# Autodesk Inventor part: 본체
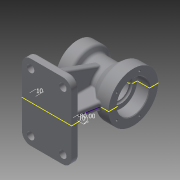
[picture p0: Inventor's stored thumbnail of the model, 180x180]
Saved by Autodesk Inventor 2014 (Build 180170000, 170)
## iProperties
Created: 2015-08
Part Number: 본체
Material: 일반
Document SubType Name: Modeling
Designer: Owner
Density: 1 g/cm^3
Appearance: 기본값
Author: Owner
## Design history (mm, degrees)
sketch "스케치1"
  geometry: L1 (-45, 0)-(45, 0); L2 (-45, 20)-(-45, 35); L3 (-45, 35)-(-25, 35); L4 (-25, 35)-(-19.804, 26); L5 (-19.804, 26)-(8.315, 26); L6 (8.315, 26)-(25, 40); L7 (25, 40)-(45, 40); L8 (45, 40)-(45, 26); L9 (45, 26)-(25, 26); L10 (22, 16)-(-28, 16); L11 (-28, 20)-(-45, 20); L12 (-28, 20)-(-28, 16); L13 (25, 26)-(25, 19); L14 (25, 19)-(22, 19); L15 (22, 19)-(22, 16); 2 further points
  constraints: 30 end point, 8 parallel, 4 perpendicular, 2 vertical alignment, 1 coincident, 1 horizontal, 1 midpoint
  dimensions: "d0" = 90 distance of L1.start L1.end; "d1" = 20 distance of L2.end L3.end; "d2" = 20 distance of L6.end L7.end; "d3" = 70 diameter of L3 L1; "d4" = 80 diameter of L7 L1; "d5" = 52 diameter of L5 L1; "d6" = 60 deg angle of L4 L5; "d7" = 40 deg angle of L5 L6; "d8" = 40 diameter of L11 L1; "d9" = 17 distance from line of L1.start L12; "d10" = 32 diameter of L10 L1; "d11" = 38 diameter of L14 L1; "d12" = 3 distance of L13.end L14.end; "d13" = 20 distance of L8.end L9.end; "d14" = 52 diameter of L9 L1
revolve "회전1" sketch "스케치1" stored, may be unused: angle "d15" = 90 deg
node "작업 평면1"
sketch "스케치2"
  geometry: L1 (25, 35)-(25, -35) reference; L2 (45, 35)-(45, -35) reference; L3 (45, 35)-(45, -35) reference; L4 (45, 35)-(25, 35) reference; L5 (45, -35)-(25, -35) reference; L6 (-35, 61)-(45, 61); L7 (45, 61)-(45, -61); L8 (45, -61)-(-35, -61); L9 (-35, -61)-(-35, 61); 2 further points
  constraints: 8 end point, 2 parallel, 1 collinear, 1 horizontal, 1 horizontal alignment, 1 midpoint, 1 perpendicular
  dimensions: "d17" = 80 distance of L7.end L8.end; "d18" = 122 distance of L6.end L7.end
extrude "돌출1" join sketch "스케치2" distance "d20" = 12; taper "d21" = 0 deg
node "작업 평면2"
sketch "스케치3"
  geometry: L1 (0, 0)-(0, 12) reference; L2 (0, 12)-(122, 12) reference; L3 (122, 12)-(122, 0) reference; L4 (122, 0)-(0, 0) reference; L5 (61, -26)-(61, 156) reference; L6 (10, 12)-(35.909, 83.185); L7 (86.091, 83.185)-(112, 12); C1 r 16 at (61, 90) reference; A1 r 26 centre (61, 90) between (35.909, 83.185) and (86.091, 83.185) reference; 1 further point
  constraints: 4 end point, 2 point on circle, 2 point on line
  dimensions: "d22" = 70 deg angle of L2 L6; "d23" = 10 distance of L6.start L1.end; "d24" = 70 deg angle of L7 L2; "d25" = 10 distance of L7.end L2.end
extrude "돌출2" join sketch "스케치3" stored distance "d26" = 12; taper "d27" = 0 deg
sketch "스케치4"
  geometry: L1 (35, 61)-(-45, 61) reference; L2 (-45, 61)-(-45, -61) reference; C1 r 6 at (-31, 47); 1 further point
  constraints: 1 centre point
  dimensions: "d28" = 12 diameter of C1; "d29" = 14 distance from line of C1.centre L1; "d30" = 14 distance from line of C1.centre L2
extrude "돌출3" cut sketch "스케치4" stored distance "d31" = 12; taper "d32" = 0 deg
fillet "모깎기1" dims "d39" = 14
node "작업 평면3"
sketch "스케치5"
  geometry: L1 (-14, 125)-(6, 125) reference; L2 (6, 125)-(11.196, 116) reference; L3 (11.196, 116)-(39.315, 116) reference; L4 (39.315, 116)-(56, 130) reference; L5 (56, 130)-(76, 130) reference; L6 (76, 130)-(76, 116) reference; L7 (76, 116)-(56, 116) reference; L8 (56, 116)-(56, 109) reference; L9 (56, 109)-(53, 109) reference; L10 (53, 109)-(53, 106) reference; L11 (53, 106)-(3, 106) reference; L12 (3, 106)-(3, 110) reference; L13 (3, 110)-(-14, 110) reference; L14 (-14, 110)-(-14, 125) reference; L15 (6, 55)-(-14, 55) reference; L16 (-14, 55)-(-14, 70) reference; L17 (-14, 70)-(3, 70) reference; L18 (3, 70)-(3, 74) reference; L19 (3, 74)-(53, 74) reference; L20 (53, 74)-(53, 71) reference; L21 (53, 71)-(56, 71) reference; L22 (56, 71)-(56, 64) reference; L23 (56, 64)-(76, 64) reference; L24 (76, 64)-(76, 50) reference; L25 (76, 50)-(56, 50) reference; L26 (56, 50)-(39.315, 64) reference; L27 (39.315, 64)-(32, 64) reference; L28 (32, 64)-(32, 12) reference; L29 (32, 12)-(66, 12) reference; L30 (66, 12)-(66, 0) reference; L31 (66, 0)-(-14, 0) reference; L32 (-14, 0)-(-14, 12) reference; L33 (-14, 12)-(20, 12) reference; L34 (20, 12)-(20, 64) reference; L35 (20, 64)-(11.196, 64) reference; L36 (11.196, 64)-(6, 55) reference; L37 (-14, 125)-(6, 125) reference; L38 (6, 125)-(11.196, 116) reference; L39 (11.196, 116)-(39.315, 116) reference; L40 (39.315, 116)-(56, 130) reference; L41 (56, 130)-(76, 130) reference; L42 (76, 130)-(76, 116) reference; L43 (76, 116)-(56, 116) reference; L44 (56, 116)-(56, 109) reference; L45 (56, 109)-(53, 109) reference; L46 (53, 109)-(53, 106) reference; L47 (53, 106)-(3, 106) reference; L48 (3, 106)-(3, 110) reference; L49 (3, 110)-(-14, 110) reference; L50 (-14, 110)-(-14, 125) reference; L51 (6, 55)-(-14, 55) reference; L52 (-14, 55)-(-14, 70) reference; L53 (-14, 70)-(3, 70) reference; L54 (3, 70)-(3, 74) reference; L55 (3, 74)-(53, 74) reference; L56 (53, 74)-(53, 71) reference; L57 (53, 71)-(56, 71) reference; L58 (56, 71)-(56, 64) reference; L59 (56, 64)-(76, 64) reference; L60 (76, 64)-(76, 50) reference; L61 (76, 50)-(56, 50) reference; L62 (56, 50)-(39.315, 64) reference; L63 (39.315, 64)-(32, 64) reference; L64 (32, 64)-(32, 12) reference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; 1 further point
  constraints: 4 end point, 3 point on line, 1 midpoint, 1 perpendicular
  dimensions: "d40" = 10 distance from line of L32 L73.start; "d41" = 10 distance from line of L74.start L30; "d42" = 80 deg angle of L74 L29
  node "절단 모서리 투영2"
  node "절단 모서리 투영3"
feature "리브1" dims "d43" = 1, "d44" = 12, "d45" = 0, "d46" = 0, "d47" = 1, "d48" = 1
feature "리브2" dims "d49" = 1, "d50" = 12, "d51" = 0, "d52" = 0, "d53" = 1, "d54" = 1
sketch "스케치6"
  geometry: C1 r 40 at (0, 0) reference; 1 further point
  constraints: 1 vertical alignment
  dimensions: "d55" = 33 distance of point (0, 33) C1.centre
hole "구멍1" sketch "스케치6" at (0, 33) diameter "d56" = 3.242; stored, may be unused: countersink angle "d60" = 90 deg, drill point angle "d62" = 118 deg; dims "d57" = 10, "d58" = 4, "d59" = 2, "d61" = 13
sketch "스케치7"
  geometry: C1 r 35 at (0, 0) reference; 1 further point
  constraints: 1 vertical alignment
  dimensions: "d66" = 27 distance of point (0, 27) C1.centre
hole "구멍2" sketch "스케치7" at (0, 27) diameter "d67" = 3.242; stored, may be unused: countersink angle "d71" = 90 deg, drill point angle "d73" = 118 deg; dims "d68" = 10, "d69" = 4, "d70" = 2, "d72" = 13
sketch "스케치8"
  geometry: L1 (112, 12)-(67, 12) reference; L2 (43, 30)-(43, 36); L3 (31, 30)-(31, 36); L4 (14, 12)-(108, 12) reference; A1 r 26 centre (61, 90) between (67, 64.702) and (86.091, 83.185) reference; A2 r 6 centre (37, 30) between (31, 30) and (43, 30); A3 r 6 centre (37, 36) between (43, 36) and (31, 36)
  constraints: 4 end point, 4 point on circle, 2 centre point, 2 tangent, 1 parallel, 1 perpendicular, 1 vertical alignment
  dimensions: "d77" = 12 diameter of A2; "d78" = 12 diameter of A3; "d79" = 24 horizontal distance of A3.centre A1.centre; "d80" = 18 distance from line of A2.centre L4; "d81" = 18 dimension on A2 A3
extrude "돌출4" cut sketch "스케치8" stored distance "d82" = 12; taper "d83" = 0 deg
node "작업 평면4"
fillet "모깎기2" dims "d84" = 0.3
chamfer "모따기1" distance "d85" = 1; stored, may be unused: second distance "d86" = 2, angle "d87" = 45 deg
fillet "모깎기3" dims "d88" = 3
fillet "모깎기4" dims "d89" = 3
fillet "모깎기5" dims "d90" = 5
fillet "모깎기6" dims "d91" = 3
sketch "스케치9"
  geometry: L1 (-3, 37.119)-(-3, 0) reference; L2 (53, -3)-(1, -3) reference; 2 further points
  constraints: 1 other
  dimensions: "d92" = 16 distance from line of point (13, 21) L1; "d93" = 24 distance from line of point (13, 21) L2
feature "엠보싱1" sketch "스케치9" dims "d0" = 90, "d1" = 20, "d2" = 20, "d3" = 70, "d4" = 80, "d5" = 52, "d6" = 60 deg, "d7" = 40 deg, "d8" = 40, "d9" = 17, "d10" = 32, "d11" = 38, "d12" = 3, "d13" = 20, "d14" = 52, "d94" = 0.5, "d95" = 0
fillet "모깎기7" dims "d96" = 3
node "솔리드1"
pattern_linear "직사각형 패턴1" dims "d35" = 52, "d38" = 94
pattern_circular "원형 패턴1" dims angle "d64" = 360 deg
pattern_circular "원형 패턴2" dims angle "d75" = 360 deg
mirror "대칭1"
node "투영된 루프1"
node "절단 모서리 투영1"
